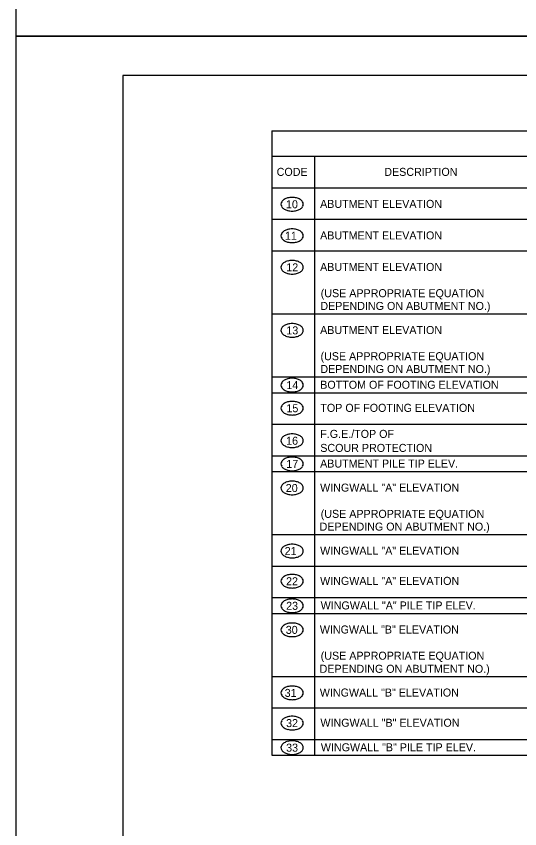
# Model space of a CAD drawing. Extents: x -5022 to -159, y 1126 to 7226.
# Drawn here: x -2158.1 to -1969.5, y 3798.9 to 4103.3 of the extents above; entities that cross this region are included whole.
import ezdxf

# ---------------------------------------------------------------- set-up
doc = ezdxf.new("R2010")
doc.units = 0
for name, color, linetype in [('2', 7, 'Continuous'), ('3', 7, 'Continuous'), ('9', 7, 'Continuous'), ('PLT-BNDY', 7, 'Continuous')]:
    doc.layers.add(name, color=color, linetype=linetype)

msp = doc.modelspace()

# ---------------------------------------------------------------- linework, layer by layer
at = {"layer": '2'}
for p, q in [((-1332.13, 4081.14), (-2118.13, 4081.14)), ((-2118.13, 4081.14), (-2118.13, 3517.14))]:
    msp.add_line(p, q, dxfattribs=at)
at = {"layer": '3'}
for centre, radius, start, end in [((-2057.32, 4032.87), 1.61, 145.8704, 180), ((-2056.09, 4032.03), 3.1, 121.4296, 145.8704), ((-2055.28, 4030.71), 4.65, 104.2049, 121.4296), ((-2054.74, 4028.6), 6.82, 90, 104.2049), ((-2054.74, 4028.6), 6.82, 75.7951, 90), ((-2054.21, 4030.71), 4.65, 58.5704, 75.7951), ((-2053.4, 4032.03), 3.1, 34.1296, 58.5704), ((-2052.17, 4032.87), 1.61, 0, 34.1296), ((-2057.32, 4032.87), 1.61, 180, 214.1296), ((-2056.09, 4033.7), 3.1, 214.1296, 238.5704), ((-2055.28, 4035.03), 4.65, 238.5704, 255.7951), ((-2054.74, 4037.13), 6.82, 255.7951, 270), ((-2054.74, 4037.13), 6.82, 270, 284.2049), ((-2054.21, 4035.03), 4.65, 284.2049, 301.4296), ((-2053.4, 4033.7), 3.1, 301.4296, 325.8704), ((-2052.17, 4032.87), 1.61, 325.8704, 0), ((-2057.32, 4021.06), 1.61, 145.8704, 180), ((-2056.09, 4020.22), 3.1, 121.4296, 145.8704), ((-2055.28, 4018.89), 4.65, 104.2049, 121.4296), ((-2054.74, 4016.79), 6.82, 90, 104.2049), ((-2054.74, 4016.79), 6.82, 75.7951, 90), ((-2054.21, 4018.89), 4.65, 58.5704, 75.7951), ((-2053.4, 4020.22), 3.1, 34.1296, 58.5704), ((-2052.17, 4021.06), 1.61, 0, 34.1296), ((-2057.32, 4021.06), 1.61, 180, 214.1296), ((-2056.09, 4021.89), 3.1, 214.1296, 238.5704), ((-2055.28, 4023.22), 4.65, 238.5704, 255.7951), ((-2054.74, 4025.32), 6.82, 255.7951, 270), ((-2054.74, 4025.32), 6.82, 270, 284.2049), ((-2054.21, 4023.22), 4.65, 284.2049, 301.4296), ((-2053.4, 4021.89), 3.1, 301.4296, 325.8704), ((-2052.17, 4021.06), 1.61, 325.8704, 0), ((-2057.32, 4009.24), 1.61, 145.8704, 180), ((-2057.32, 4009.24), 1.61, 180, 214.1296), ((-2056.09, 4008.41), 3.1, 121.4296, 145.8704), ((-2055.28, 4007.08), 4.65, 104.2049, 121.4296), ((-2054.74, 4004.98), 6.82, 90, 104.2049), ((-2054.74, 4004.98), 6.82, 75.7951, 90), ((-2054.21, 4007.08), 4.65, 58.5704, 75.7951), ((-2053.4, 4008.41), 3.1, 34.1296, 58.5704), ((-2052.17, 4009.24), 1.61, 0, 34.1296), ((-2052.17, 4009.24), 1.61, 325.8704, 0), ((-2056.09, 4010.08), 3.1, 214.1296, 238.5704), ((-2055.28, 4011.41), 4.65, 238.5704, 255.7951), ((-2054.74, 4013.51), 6.82, 255.7951, 270), ((-2054.74, 4013.51), 6.82, 270, 284.2049), ((-2054.21, 4011.41), 4.65, 284.2049, 301.4296), ((-2053.4, 4010.08), 3.1, 301.4296, 325.8704), ((-2055.28, 3983.46), 4.65, 104.2049, 121.4296), ((-2054.74, 3981.35), 6.82, 90, 104.2049), ((-2054.74, 3981.35), 6.82, 75.7951, 90), ((-2054.21, 3983.46), 4.65, 58.5704, 75.7951), ((-2057.32, 3985.62), 1.61, 145.8704, 180), ((-2057.32, 3985.62), 1.61, 180, 214.1296), ((-2056.09, 3984.79), 3.1, 121.4296, 145.8704), ((-2053.4, 3984.79), 3.1, 34.1296, 58.5704), ((-2052.17, 3985.62), 1.61, 0, 34.1296), ((-2052.17, 3985.62), 1.61, 325.8704, 0), ((-2056.09, 3986.45), 3.1, 214.1296, 238.5704), ((-2055.28, 3987.78), 4.65, 238.5704, 255.7951), ((-2054.74, 3989.89), 6.82, 255.7951, 270), ((-2054.74, 3989.89), 6.82, 270, 284.2049), ((-2054.21, 3987.78), 4.65, 284.2049, 301.4296), ((-2053.4, 3986.45), 3.1, 301.4296, 325.8704), ((-2056.09, 3964.28), 3.1, 121.4296, 145.8704), ((-2055.28, 3962.95), 4.65, 104.2049, 121.4296), ((-2054.74, 3960.84), 6.82, 90, 104.2049), ((-2054.74, 3960.84), 6.82, 75.7951, 90), ((-2054.21, 3962.95), 4.65, 58.5704, 75.7951), ((-2053.4, 3964.28), 3.1, 34.1296, 58.5704), ((-2057.32, 3965.11), 1.61, 145.8704, 180), ((-2057.32, 3965.11), 1.61, 180, 214.1296), ((-2056.09, 3965.94), 3.1, 214.1296, 238.5704), ((-2053.4, 3965.94), 3.1, 301.4296, 325.8704), ((-2052.17, 3965.11), 1.61, 0, 34.1296), ((-2052.17, 3965.11), 1.61, 325.8704, 0), ((-2055.28, 3967.27), 4.65, 238.5704, 255.7951), ((-2054.74, 3969.38), 6.82, 255.7951, 270), ((-2054.74, 3969.38), 6.82, 270, 284.2049), ((-2054.21, 3967.27), 4.65, 284.2049, 301.4296), ((-2056.09, 3955.62), 3.1, 121.4296, 145.8704), ((-2055.28, 3954.29), 4.65, 104.2049, 121.4296), ((-2054.74, 3952.19), 6.82, 90, 104.2049), ((-2054.74, 3952.19), 6.82, 75.7951, 90), ((-2054.21, 3954.29), 4.65, 58.5704, 75.7951), ((-2053.4, 3955.62), 3.1, 34.1296, 58.5704), ((-2057.32, 3956.45), 1.61, 145.8704, 180), ((-2057.32, 3956.45), 1.61, 180, 214.1296), ((-2056.09, 3957.29), 3.1, 214.1296, 238.5704), ((-2055.28, 3958.62), 4.65, 238.5704, 255.7951), ((-2054.21, 3958.62), 4.65, 284.2049, 301.4296), ((-2053.4, 3957.29), 3.1, 301.4296, 325.8704), ((-2052.17, 3956.45), 1.61, 0, 34.1296), ((-2052.17, 3956.45), 1.61, 325.8704, 0), ((-2054.74, 3960.72), 6.82, 255.7951, 270), ((-2054.74, 3960.72), 6.82, 270, 284.2049), ((-2056.09, 3943.45), 3.1, 121.4296, 145.8704), ((-2055.28, 3942.12), 4.65, 104.2049, 121.4296), ((-2054.74, 3940.01), 6.82, 90, 104.2049), ((-2054.74, 3940.01), 6.82, 75.7951, 90), ((-2054.21, 3942.12), 4.65, 58.5704, 75.7951), ((-2053.4, 3943.45), 3.1, 34.1296, 58.5704), ((-2057.32, 3944.28), 1.61, 145.8704, 180), ((-2057.32, 3944.28), 1.61, 180, 214.1296), ((-2056.09, 3945.11), 3.1, 214.1296, 238.5704), ((-2055.28, 3946.44), 4.65, 238.5704, 255.7951), ((-2054.21, 3946.44), 4.65, 284.2049, 301.4296), ((-2053.4, 3945.11), 3.1, 301.4296, 325.8704), ((-2052.17, 3944.28), 1.61, 0, 34.1296), ((-2052.17, 3944.28), 1.61, 325.8704, 0), ((-2054.74, 3948.55), 6.82, 255.7951, 270), ((-2054.74, 3948.55), 6.82, 270, 284.2049), ((-2057.32, 3935.58), 1.61, 145.8704, 180), ((-2056.09, 3934.75), 3.1, 121.4296, 145.8704), ((-2055.28, 3933.42), 4.65, 104.2049, 121.4296), ((-2054.74, 3931.31), 6.82, 90, 104.2049), ((-2054.74, 3931.31), 6.82, 75.7951, 90), ((-2054.21, 3933.42), 4.65, 58.5704, 75.7951), ((-2053.4, 3934.75), 3.1, 34.1296, 58.5704), ((-2052.17, 3935.58), 1.61, 0, 34.1296), ((-2057.32, 3935.58), 1.61, 180, 214.1296), ((-2056.09, 3936.41), 3.1, 214.1296, 238.5704), ((-2055.28, 3937.74), 4.65, 238.5704, 255.7951), ((-2054.74, 3939.85), 6.82, 255.7951, 270), ((-2054.74, 3939.85), 6.82, 270, 284.2049), ((-2054.21, 3937.74), 4.65, 284.2049, 301.4296), ((-2053.4, 3936.41), 3.1, 301.4296, 325.8704), ((-2052.17, 3935.58), 1.61, 325.8704, 0), ((-2057.32, 3926.56), 1.61, 145.8704, 180), ((-2056.09, 3925.73), 3.1, 121.4296, 145.8704), ((-2055.28, 3924.4), 4.65, 104.2049, 121.4296), ((-2054.74, 3922.3), 6.82, 90, 104.2049), ((-2054.74, 3922.3), 6.82, 75.7951, 90), ((-2054.21, 3924.4), 4.65, 58.5704, 75.7951), ((-2053.4, 3925.73), 3.1, 34.1296, 58.5704), ((-2052.17, 3926.56), 1.61, 0, 34.1296), ((-2057.32, 3926.56), 1.61, 180, 214.1296), ((-2056.09, 3927.4), 3.1, 214.1296, 238.5704), ((-2055.28, 3928.73), 4.65, 238.5704, 255.7951), ((-2054.74, 3930.83), 6.82, 255.7951, 270), ((-2054.74, 3930.83), 6.82, 270, 284.2049), ((-2054.21, 3928.73), 4.65, 284.2049, 301.4296), ((-2053.4, 3927.4), 3.1, 301.4296, 325.8704), ((-2052.17, 3926.56), 1.61, 325.8704, 0), ((-2057.32, 3902.94), 1.61, 145.8704, 180), ((-2057.32, 3902.94), 1.61, 180, 214.1296), ((-2056.09, 3902.11), 3.1, 121.4296, 145.8704), ((-2055.28, 3900.78), 4.65, 104.2049, 121.4296), ((-2054.74, 3898.67), 6.82, 90, 104.2049), ((-2054.74, 3898.67), 6.82, 75.7951, 90), ((-2054.21, 3900.78), 4.65, 58.5704, 75.7951), ((-2053.4, 3902.11), 3.1, 34.1296, 58.5704), ((-2052.17, 3902.94), 1.61, 0, 34.1296), ((-2052.17, 3902.94), 1.61, 325.8704, 0), ((-2056.09, 3903.78), 3.1, 214.1296, 238.5704), ((-2055.28, 3905.1), 4.65, 238.5704, 255.7951), ((-2054.74, 3907.21), 6.82, 255.7951, 270), ((-2054.74, 3907.21), 6.82, 270, 284.2049), ((-2054.21, 3905.1), 4.65, 284.2049, 301.4296), ((-2053.4, 3903.78), 3.1, 301.4296, 325.8704), ((-2055.28, 3889.47), 4.65, 104.2049, 121.4296), ((-2054.74, 3887.36), 6.82, 90, 104.2049), ((-2054.74, 3887.36), 6.82, 75.7951, 90), ((-2054.21, 3889.47), 4.65, 58.5704, 75.7951), ((-2057.32, 3891.63), 1.61, 145.8704, 180), ((-2057.32, 3891.63), 1.61, 180, 214.1296), ((-2056.09, 3890.8), 3.1, 121.4296, 145.8704), ((-2056.09, 3892.47), 3.1, 214.1296, 238.5704), ((-2053.4, 3890.8), 3.1, 34.1296, 58.5704), ((-2053.4, 3892.47), 3.1, 301.4296, 325.8704), ((-2052.17, 3891.63), 1.61, 0, 34.1296), ((-2052.17, 3891.63), 1.61, 325.8704, 0), ((-2055.28, 3893.79), 4.65, 238.5704, 255.7951), ((-2054.74, 3895.9), 6.82, 255.7951, 270), ((-2054.74, 3895.9), 6.82, 270, 284.2049), ((-2054.21, 3893.79), 4.65, 284.2049, 301.4296), ((-2055.28, 3880.27), 4.65, 104.2049, 121.4296), ((-2054.74, 3878.16), 6.82, 90, 104.2049), ((-2054.74, 3878.16), 6.82, 75.7951, 90), ((-2054.21, 3880.27), 4.65, 58.5704, 75.7951), ((-2057.32, 3882.43), 1.61, 145.8704, 180), ((-2057.32, 3882.43), 1.61, 180, 214.1296), ((-2056.09, 3881.6), 3.1, 121.4296, 145.8704), ((-2056.09, 3883.26), 3.1, 214.1296, 238.5704), ((-2053.4, 3881.6), 3.1, 34.1296, 58.5704), ((-2053.4, 3883.26), 3.1, 301.4296, 325.8704), ((-2052.17, 3882.43), 1.61, 0, 34.1296), ((-2052.17, 3882.43), 1.61, 325.8704, 0), ((-2055.28, 3884.59), 4.65, 238.5704, 255.7951), ((-2054.74, 3886.7), 6.82, 255.7951, 270), ((-2054.74, 3886.7), 6.82, 270, 284.2049), ((-2054.21, 3884.59), 4.65, 284.2049, 301.4296), ((-2055.28, 3871.25), 4.65, 104.2049, 121.4296), ((-2054.74, 3869.15), 6.82, 90, 104.2049), ((-2054.74, 3869.15), 6.82, 75.7951, 90), ((-2054.21, 3871.25), 4.65, 58.5704, 75.7951), ((-2057.32, 3873.41), 1.61, 145.8704, 180), ((-2057.32, 3873.41), 1.61, 180, 214.1296), ((-2056.09, 3872.58), 3.1, 121.4296, 145.8704), ((-2056.09, 3874.25), 3.1, 214.1296, 238.5704), ((-2053.4, 3872.58), 3.1, 34.1296, 58.5704), ((-2053.4, 3874.25), 3.1, 301.4296, 325.8704), ((-2052.17, 3873.41), 1.61, 0, 34.1296), ((-2052.17, 3873.41), 1.61, 325.8704, 0), ((-2055.28, 3875.58), 4.65, 238.5704, 255.7951), ((-2054.74, 3877.68), 6.82, 255.7951, 270), ((-2054.74, 3877.68), 6.82, 270, 284.2049), ((-2054.21, 3875.58), 4.65, 284.2049, 301.4296), ((-2056.09, 3848.96), 3.1, 121.4296, 145.8704), ((-2055.28, 3847.63), 4.65, 104.2049, 121.4296), ((-2054.74, 3845.52), 6.82, 90, 104.2049), ((-2054.74, 3845.52), 6.82, 75.7951, 90), ((-2054.21, 3847.63), 4.65, 58.5704, 75.7951), ((-2053.4, 3848.96), 3.1, 34.1296, 58.5704), ((-2057.32, 3849.79), 1.61, 145.8704, 180), ((-2057.32, 3849.79), 1.61, 180, 214.1296), ((-2056.09, 3850.62), 3.1, 214.1296, 238.5704), ((-2055.28, 3851.95), 4.65, 238.5704, 255.7951), ((-2054.21, 3851.95), 4.65, 284.2049, 301.4296), ((-2053.4, 3850.62), 3.1, 301.4296, 325.8704), ((-2052.17, 3849.79), 1.61, 0, 34.1296), ((-2052.17, 3849.79), 1.61, 325.8704, 0), ((-2054.74, 3854.06), 6.82, 255.7951, 270), ((-2054.74, 3854.06), 6.82, 270, 284.2049), ((-2057.32, 3838.48), 1.61, 145.8704, 180), ((-2056.09, 3837.65), 3.1, 121.4296, 145.8704), ((-2055.28, 3836.32), 4.65, 104.2049, 121.4296), ((-2054.74, 3834.21), 6.82, 90, 104.2049), ((-2054.74, 3834.21), 6.82, 75.7951, 90), ((-2054.21, 3836.32), 4.65, 58.5704, 75.7951), ((-2053.4, 3837.65), 3.1, 34.1296, 58.5704), ((-2052.17, 3838.48), 1.61, 0, 34.1296), ((-2057.32, 3838.48), 1.61, 180, 214.1296), ((-2056.09, 3839.31), 3.1, 214.1296, 238.5704), ((-2055.28, 3840.64), 4.65, 238.5704, 255.7951), ((-2054.74, 3842.75), 6.82, 255.7951, 270), ((-2054.74, 3842.75), 6.82, 270, 284.2049), ((-2054.21, 3840.64), 4.65, 284.2049, 301.4296), ((-2053.4, 3839.31), 3.1, 301.4296, 325.8704), ((-2052.17, 3838.48), 1.61, 325.8704, 0), ((-2057.32, 3829.28), 1.61, 145.8704, 180), ((-2056.09, 3828.44), 3.1, 121.4296, 145.8704), ((-2055.28, 3827.12), 4.65, 104.2049, 121.4296), ((-2054.74, 3825.01), 6.82, 90, 104.2049), ((-2054.74, 3825.01), 6.82, 75.7951, 90), ((-2054.21, 3827.12), 4.65, 58.5704, 75.7951), ((-2053.4, 3828.44), 3.1, 34.1296, 58.5704), ((-2052.17, 3829.28), 1.61, 0, 34.1296), ((-2057.32, 3829.28), 1.61, 180, 214.1296), ((-2056.09, 3830.11), 3.1, 214.1296, 238.5704), ((-2055.28, 3831.44), 4.65, 238.5704, 255.7951), ((-2054.74, 3833.55), 6.82, 255.7951, 270), ((-2054.74, 3833.55), 6.82, 270, 284.2049), ((-2054.21, 3831.44), 4.65, 284.2049, 301.4296), ((-2053.4, 3830.11), 3.1, 301.4296, 325.8704), ((-2052.17, 3829.28), 1.61, 325.8704, 0)]:
    msp.add_arc(centre, radius, start, end, dxfattribs=at)
at = {"layer": '9'}
for p, q in [((-2062.32, 4060.39), (-1738.15, 4060.39)), ((-2062.32, 4060.39), (-2062.32, 3826.43)), ((-2062.32, 4050.85), (-1738.15, 4050.85)), ((-2046.38, 4050.85), (-2046.38, 3826.43)), ((-2062.32, 4039.04), (-1738.15, 4039.04)), ((-2062.32, 4027.22), (-1738.15, 4027.22)), ((-2062.32, 4015.41), (-1738.15, 4015.41)), ((-2062.32, 3991.79), (-1738.15, 3991.79)), ((-2062.32, 3968.17), (-1738.15, 3968.17)), ((-2062.32, 3962.26), (-1738.15, 3962.26)), ((-2062.32, 3950.45), (-1738.15, 3950.45)), ((-2062.32, 3938.64), (-1738.15, 3938.64)), ((-2062.32, 3932.73), (-1738.15, 3932.73)), ((-2062.32, 3909.11), (-1738.15, 3909.11)), ((-2062.32, 3897.3), (-1738.15, 3897.3)), ((-2062.32, 3885.49), (-1738.15, 3885.49)), ((-2062.32, 3879.58), (-1738.15, 3879.58)), ((-2062.32, 3855.96), (-1738.15, 3855.96)), ((-2062.32, 3844.15), (-1738.15, 3844.15)), ((-2062.32, 3832.34), (-1738.15, 3832.34)), ((-2062.32, 3826.43), (-1738.15, 3826.43))]:
    msp.add_line(p, q, dxfattribs=at)
at = {"layer": 'PLT-BNDY'}
for points in [[(-2158.13, 4689.81), (-1317.13, 4689.81), (-1317.13, 4095.81), (-2158.13, 4095.81)], [(-2158.13, 4095.81), (-1317.13, 4095.81), (-1317.13, 3501.81), (-2158.13, 3501.81)]]:
    msp.add_lwpolyline(points, close=True, dxfattribs=at)

# ---------------------------------------------------------------- texts
at = {"layer": '3'}
for s, height, p in [('CODE', 3, (-2060.54, 4043.5)), ('DESCRIPTION', 3.0001, (-2020.21, 4043.5)), ('10', 3, (-2057.04, 4031.36)), ('ABUTMENT ELEVATION', 3.0001, (-2044.26, 4031.5)), ('11', 3, (-2057.46, 4019.54)), ('ABUTMENT ELEVATION', 3.0001, (-2044.26, 4019.69)), ('12', 3, (-2056.94, 4007.73)), ('ABUTMENT ELEVATION', 3.0001, (-2044.26, 4007.88)), ('(USE APPROPRIATE EQUATION', 3.0001, (-2044.04, 3998.05)), ('DEPENDING ON ABUTMENT NO.)', 3.0001, (-2044.17, 3993.27)), ('13', 3, (-2056.92, 3984.11)), ('ABUTMENT ELEVATION', 3.0001, (-2044.26, 3984.25)), ('(USE APPROPRIATE EQUATION', 3.0001, (-2044.11, 3974.43)), ('DEPENDING ON ABUTMENT NO.)', 3.0001, (-2044.17, 3969.65)), ('14', 3, (-2056.91, 3963.6)), ('BOTTOM OF FOOTING ELEVATION', 3.0001, (-2044.22, 3963.74)), ('15', 3, (-2056.88, 3954.95)), ('TOP OF FOOTING ELEVATION', 3.0001, (-2044.17, 3955.09)), ('F.G.E./TOP OF', 2.9998, (-2044.2, 3945.33)), ('16', 3, (-2057, 3942.77)), ('SCOUR PROTECTION', 2.9998, (-2044.2, 3940.08)), ('17', 3, (-2056.92, 3934.07)), ('ABUTMENT PILE TIP ELEV.', 3.0001, (-2044.26, 3934.21)), ('20', 3, (-2057.13, 3925.05)), ('WINGWALL "A" ELEVATION', 3.0001, (-2044.26, 3925.2)), ('(USE APPROPRIATE EQUATION', 3.0001, (-2044.04, 3915.37)), ('DEPENDING ON ABUTMENT NO.)', 3.0001, (-2044.45, 3910.59)), ('21', 3, (-2057.54, 3901.43)), ('WINGWALL "A" ELEVATION', 3.0001, (-2044.26, 3901.57)), ('22', 3, (-2057.02, 3890.12)), ('WINGWALL "A" ELEVATION', 3.0001, (-2044.26, 3890.26)), ('23', 3, (-2057, 3880.92)), ('WINGWALL "A" PILE TIP ELEV.', 3.0001, (-2044.06, 3881.06)), ('30', 3, (-2057.13, 3871.9)), ('WINGWALL "B" ELEVATION', 3.0001, (-2044.37, 3872.04)), ('(USE APPROPRIATE EQUATION', 3.0001, (-2044.04, 3862.22)), ('DEPENDING ON ABUTMENT NO.)', 3.0001, (-2044.45, 3857.32)), ('31', 3, (-2057.54, 3848.28)), ('WINGWALL "B" ELEVATION', 3.0001, (-2044.37, 3848.42)), ('32', 3, (-2057.02, 3836.97)), ('WINGWALL "B" ELEVATION', 3.0001, (-2044.15, 3837.11)), ('33', 3, (-2057, 3827.77)), ('WINGWALL "B" PILE TIP ELEV.', 3.0001, (-2043.99, 3827.91))]:
    msp.add_text(s, height=height, dxfattribs=at).set_placement(p)

doc.saveas('drawing.dxf')
